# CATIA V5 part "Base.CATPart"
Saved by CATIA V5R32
Part number: Part1
Bounding box of the stored display mesh (mm): x -50 to 50, y -25 to 25, z 0 to 50
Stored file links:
  D:\PROJECTS\Project 2022\CATIA V5 6R 2022\Resources\Part Files\c12_catia_v5_6r2022_prt\c12_catia_v5-6r2022 figr_12-12\Base.CATPart
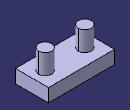
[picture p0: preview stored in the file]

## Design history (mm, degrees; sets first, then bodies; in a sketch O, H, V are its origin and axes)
Body1 (main body)
  Sketch1 on xy-plane, origin (0, 0, 0), H (1, 0, 0), V (0, 1, 0)
    line L1 (50, 25) -> (50, -25)
    line L2 (50, -25) -> (-50, -25)
    line L3 (-50, -25) -> (-50, 25)
    line L4 (-50, 25) -> (50, 25)
    circle A1 centre (-30, 0) radius 10
    point P5 (-30, 0)
    circle A2 centre (30, 0) radius 10
    length L2 = 100
    length L1 = 50
    radius A1 = 10
    distance P5 V = 30
    vertical: L1 V, L3 V
    horizontal: L2 H, L4 H
    equidistance: L1 L3 O, L2 L4 O
    coincidence: P5 H
    symmetry: A1 A2 V
  MultiPad1: profile Sketch1, domains (length 20; length 50; length 50)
